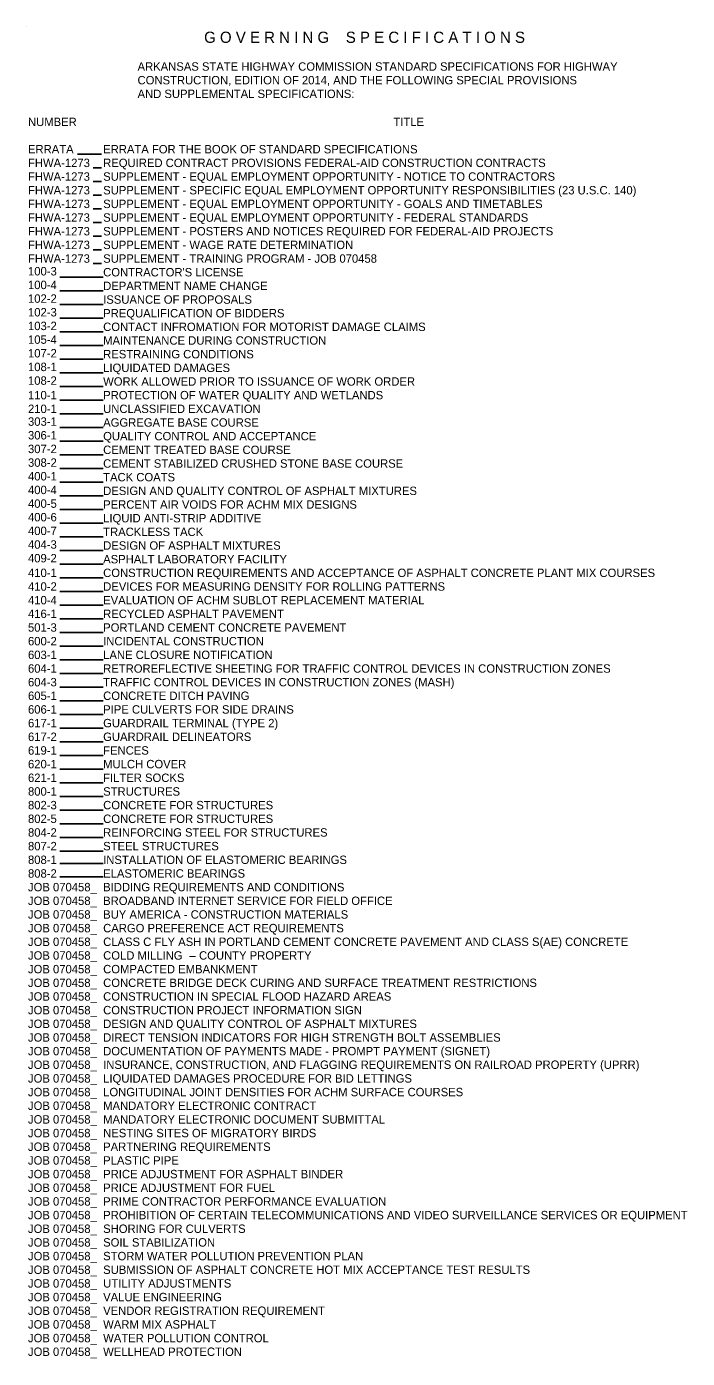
# Model space of a CAD drawing. Extents: x -2857 to 1648, y -1031 to 968.
# Drawn here: x -1360 to -417, y -932 to 968 of the extents above; entities that cross this region are included whole.
import ezdxf

# ---------------------------------------------------------------- set-up
doc = ezdxf.new("R2010")
doc.units = 0
doc.layers.add('Default', color=7, linetype='Continuous')

msp = doc.modelspace()

# ---------------------------------------------------------------- linework, layer by layer
at = {"layer": 'Default'}
for p, q in [((-1359.5, 967.9), (-1359.5, 967.9)), ((-1287.2, 785.9), (-1252.7, 785.9)), ((-1264.8, 766.4), (-1252.7, 766.4)), ((-1264.8, 746.9), (-1252.7, 746.9)), ((-1264.8, 727.4), (-1252.7, 727.4)), ((-1264.8, 707.9), (-1252.7, 707.9)), ((-1264.8, 688.4), (-1252.7, 688.4)), ((-1264.8, 668.9), (-1252.7, 668.9)), ((-1264.8, 649.4), (-1252.7, 649.4)), ((-1264.8, 629.9), (-1252.7, 629.9)), ((-1312.4, 610.4), (-1250.6, 610.4)), ((-1312.4, 590.9), (-1250.6, 590.9)), ((-1312.4, 571.4), (-1250.6, 571.4)), ((-1312.4, 551.9), (-1250.6, 551.9)), ((-1312.4, 532.4), (-1250.6, 532.4)), ((-1312.4, 512.9), (-1250.6, 512.9)), ((-1312.4, 493.4), (-1250.6, 493.4)), ((-1312.4, 473.9), (-1250.6, 473.9)), ((-1312.4, 454.4), (-1250.6, 454.4)), ((-1312.4, 434.9), (-1250.6, 434.9)), ((-1312.4, 415.4), (-1250.6, 415.4)), ((-1312.4, 395.9), (-1250.6, 395.9)), ((-1312.4, 376.4), (-1250.6, 376.4)), ((-1312.4, 356.9), (-1250.6, 356.9)), ((-1312.4, 337.4), (-1250.6, 337.4)), ((-1312.4, 317.9), (-1250.6, 317.9)), ((-1312.4, 298.4), (-1250.6, 298.4)), ((-1312.4, 278.9), (-1250.6, 278.9)), ((-1312.4, 259.4), (-1250.6, 259.4)), ((-1312.4, 239.9), (-1250.6, 239.9)), ((-1312.4, 220.4), (-1250.6, 220.4)), ((-1312.4, 200.9), (-1250.6, 200.9)), ((-1312.4, 181.4), (-1250.6, 181.4)), ((-1312.4, 161.9), (-1250.6, 161.9)), ((-1312.4, 142.4), (-1250.6, 142.4)), ((-1312.4, 122.9), (-1250.6, 122.9)), ((-1312.4, 103.4), (-1250.6, 103.4)), ((-1312.4, 83.9), (-1250.6, 83.9)), ((-1312.4, 64.4), (-1250.6, 64.4)), ((-1312.4, 44.9), (-1250.6, 44.9)), ((-1312.4, 25.4), (-1250.6, 25.4)), ((-1312.4, 5.9), (-1250.6, 5.9)), ((-1312.4, -13.6), (-1250.6, -13.6)), ((-1312.4, -33.1), (-1250.6, -33.1)), ((-1312.4, -52.6), (-1250.6, -52.6)), ((-1312.4, -72.1), (-1250.6, -72.1)), ((-1312.4, -91.6), (-1250.6, -91.6)), ((-1312.4, -111.1), (-1250.6, -111.1)), ((-1312.4, -130.6), (-1250.6, -130.6)), ((-1312.4, -150.1), (-1250.6, -150.1)), ((-1312.4, -169.6), (-1250.6, -169.6)), ((-1312.4, -189.1), (-1250.6, -189.1)), ((-1312.4, -208.6), (-1250.6, -208.6)), ((-1312.4, -226.2), (-1250.6, -226.2)), ((-1312.4, -245.3), (-1250.6, -245.3))]:
    msp.add_line(p, q, dxfattribs=at)

# ---------------------------------------------------------------- texts
for s, height, p in [('G O V E R N I N G    S P E C I F I C A T I O N S', 15.997, (-1106.4, 944.7)), ('           ARKANSAS STATE HIGHWAY COMMISSION STANDARD SPECIFICATIONS FOR HIGHWAY', 11.998, (-1250.4, 905)), ('           CONSTRUCTION, EDITION OF 2014, AND THE FOLLOWING SPECIAL PROVISIONS', 11.998, (-1250.4, 885.5)), ('           AND SUPPLEMENTAL SPECIFICATIONS:', 11.998, (-1250.4, 866)), ('NUMBER', 12, (-1357.6, 826)), ('TITLE', 12, (-836.5, 826)), ('ERRATA', 12, (-1357.6, 787)), ('ERRATA FOR THE BOOK OF STANDARD SPECIFICATIONS', 11.998, (-1250.4, 787)), ('FHWA-1273', 12, (-1357.6, 767.5)), ('REQUIRED CONTRACT PROVISIONS FEDERAL-AID CONSTRUCTION CONTRACTS', 11.998, (-1250.4, 767.5)), ('FHWA-1273', 12, (-1357.6, 748)), ('SUPPLEMENT - EQUAL EMPLOYMENT OPPORTUNITY - NOTICE TO CONTRACTORS', 11.998, (-1250.4, 748)), ('SUPPLEMENT - SPECIFIC EQUAL EMPLOYMENT OPPORTUNITY RESPONSIBILITIES (23 U.S.C. 140)', 11.998, (-1250.4, 728.5)), ('FHWA-1273', 12, (-1357.6, 728.5)), ('FHWA-1273', 12, (-1357.6, 709)), ('SUPPLEMENT - EQUAL EMPLOYMENT OPPORTUNITY - GOALS AND TIMETABLES ', 11.998, (-1250.4, 709)), ('FHWA-1273', 12, (-1357.6, 689.5)), ('SUPPLEMENT - EQUAL EMPLOYMENT OPPORTUNITY - FEDERAL STANDARDS', 11.998, (-1250.4, 689.5)), ('FHWA-1273', 12, (-1357.6, 670)), ('SUPPLEMENT - POSTERS AND NOTICES REQUIRED FOR FEDERAL-AID PROJECTS', 11.998, (-1250.4, 670)), ('FHWA-1273', 12, (-1357.6, 650.5)), ('SUPPLEMENT - WAGE RATE DETERMINATION', 11.998, (-1250.4, 650.5)), ('FHWA-1273', 12, (-1357.6, 631)), ('SUPPLEMENT - TRAINING PROGRAM - JOB 070458', 11.998, (-1250.4, 631)), ('100-3', 12, (-1357.6, 612.9)), ("CONTRACTOR'S LICENSE", 11.998, (-1250.4, 611.5)), ('100-4', 12, (-1357.6, 593.4)), ('DEPARTMENT NAME CHANGE', 11.998, (-1250.4, 592)), ('102-2', 12, (-1357.6, 573.9)), ('ISSUANCE OF PROPOSALS', 11.998, (-1250.4, 572.5)), ('102-3', 12, (-1357.6, 554.4)), ('PREQUALIFICATION OF BIDDERS', 11.998, (-1250.4, 553)), ('103-2', 12, (-1357.6, 534.9)), ('CONTACT INFROMATION FOR MOTORIST DAMAGE CLAIMS', 11.998, (-1250.4, 533.6)), ('105-4', 12, (-1357.6, 515.4)), ('MAINTENANCE DURING CONSTRUCTION', 11.998, (-1250.4, 514.1)), ('107-2', 12, (-1357.6, 495.9)), ('RESTRAINING CONDITIONS', 11.998, (-1250.4, 494.6)), ('108-1', 12, (-1357.6, 476.4)), ('LIQUIDATED DAMAGES', 11.998, (-1250.4, 475.1)), ('108-2', 12, (-1357.6, 456.9)), ('WORK ALLOWED PRIOR TO ISSUANCE OF WORK ORDER', 11.998, (-1250.4, 455.6)), ('110-1', 12, (-1357.6, 436.1)), ('PROTECTION OF WATER QUALITY AND WETLANDS', 11.998, (-1250.4, 436.1)), ('210-1', 12, (-1357.6, 416.6)), ('UNCLASSIFIED EXCAVATION', 11.998, (-1250.4, 416.6)), ('303-1', 12, (-1357.6, 398.4)), ('AGGREGATE BASE COURSE', 11.998, (-1250.4, 397.1)), ('306-1', 12, (-1357.6, 378.9)), ('QUALITY CONTROL AND ACCEPTANCE', 11.998, (-1250.4, 377.6)), ('307-2', 12, (-1357.6, 359.4)), ('CEMENT TREATED BASE COURSE', 11.998, (-1250.4, 358.1)), ('308-2', 12, (-1357.6, 339.9)), ('CEMENT STABILIZED CRUSHED STONE BASE COURSE', 11.998, (-1250.4, 338.6)), ('400-1', 12, (-1357.6, 320.4)), ('TACK COATS', 12, (-1250.4, 319.1)), ('400-4', 12, (-1357.6, 300.9)), ('DESIGN AND QUALITY CONTROL OF ASPHALT MIXTURES', 11.998, (-1250.4, 299.6)), ('400-5', 12, (-1357.6, 281.4)), ('PERCENT AIR VOIDS FOR ACHM MIX DESIGNS', 11.998, (-1250.4, 280.1)), ('400-6', 12, (-1357.6, 262)), ('LIQUID ANTI-STRIP ADDITIVE', 11.998, (-1250.4, 260.6)), ('400-7', 12, (-1357.6, 242.5)), ('TRACKLESS TACK', 11.998, (-1250.4, 241.1)), ('404-3', 12, (-1357.6, 223)), ('DESIGN OF ASPHALT MIXTURES', 11.998, (-1250.4, 221.6)), ('409-2', 12, (-1357.6, 203.5)), ('ASPHALT LABORATORY FACILITY', 11.998, (-1250.4, 202.1)), ('410-1', 12, (-1357.6, 182.6)), ('CONSTRUCTION REQUIREMENTS AND ACCEPTANCE OF ASPHALT CONCRETE PLANT MIX COURSES', 11.998, (-1250.4, 182.6)), ('410-2', 12, (-1357.6, 163.1)), ('DEVICES FOR MEASURING DENSITY FOR ROLLING PATTERNS', 11.998, (-1250.4, 163.1)), ('410-4', 12, (-1357.6, 143.6)), ('EVALUATION OF ACHM SUBLOT REPLACEMENT MATERIAL', 11.998, (-1250.4, 143.6)), ('416-1', 12, (-1357.6, 124.1)), ('RECYCLED ASPHALT PAVEMENT', 11.998, (-1250.4, 124.1)), ('501-3', 12, (-1357.6, 104.6)), ('PORTLAND CEMENT CONCRETE PAVEMENT', 11.998, (-1250.4, 104.6)), ('600-2', 12, (-1357.6, 85.1)), ('INCIDENTAL CONSTRUCTION', 11.998, (-1250.4, 85.1)), ('603-1', 12, (-1357.6, 65.6)), ('LANE CLOSURE NOTIFICATION', 11.998, (-1250.4, 65.6)), ('604-1', 12, (-1357.6, 46.1)), ('RETROREFLECTIVE SHEETING FOR TRAFFIC CONTROL DEVICES IN CONSTRUCTION ZONES', 11.998, (-1250.4, 46.1)), ('604-3', 12, (-1357.6, 26.6)), ('TRAFFIC CONTROL DEVICES IN CONSTRUCTION ZONES (MASH)', 11.998, (-1250.4, 26.6)), ('605-1', 12, (-1357.6, 7.2)), ('CONCRETE DITCH PAVING', 11.998, (-1250.4, 7.2)), ('606-1', 12, (-1357.6, -12.3)), ('PIPE CULVERTS FOR SIDE DRAINS', 11.998, (-1250.4, -12.3)), ('617-1', 12, (-1357.6, -31.8)), ('GUARDRAIL TERMINAL (TYPE 2)', 11.998, (-1250.4, -31.8)), ('617-2', 12, (-1357.6, -51.3)), ('GUARDRAIL DELINEATORS', 11.998, (-1250.4, -51.3)), ('619-1', 12, (-1357.6, -70.8)), ('FENCES', 12, (-1250.4, -70.8)), ('620-1', 12, (-1357.6, -90.3)), ('MULCH COVER', 11.998, (-1250.4, -90.3)), ('621-1', 12, (-1357.6, -109.8)), ('FILTER SOCKS', 11.998, (-1250.4, -109.8)), ('800-1', 12, (-1357.6, -129.3)), ('STRUCTURES', 12, (-1250.4, -129.3)), ('802-3', 12, (-1357.6, -148.8)), ('CONCRETE FOR STRUCTURES', 11.998, (-1250.4, -148.8)), ('802-5', 12, (-1357.6, -168.3)), ('CONCRETE FOR STRUCTURES', 11.998, (-1250.4, -168.3)), ('804-2', 12, (-1357.6, -187.8)), ('REINFORCING STEEL FOR STRUCTURES', 11.998, (-1250.4, -187.8)), ('807-2', 12, (-1357.6, -207.3)), ('STEEL STRUCTURES', 11.998, (-1250.4, -207.3)), ('808-1', 12, (-1357.6, -226.8)), ('INSTALLATION OF ELASTOMERIC BEARINGS', 11.998, (-1250.4, -226.8)), ('808-2', 12, (-1357.6, -246.3)), ('ELASTOMERIC BEARINGS', 11.998, (-1250.4, -246.3)), ('JOB 070458_', 11.998, (-1357.6, -265.8)), ('BIDDING REQUIREMENTS AND CONDITIONS', 11.998, (-1250.4, -265.8)), ('JOB 070458_', 11.998, (-1357.6, -285.3)), ('BROADBAND INTERNET SERVICE FOR FIELD OFFICE', 11.998, (-1250.4, -285.3)), ('JOB 070458_', 11.998, (-1357.6, -304.8)), ('BUY AMERICA - CONSTRUCTION MATERIALS', 11.998, (-1250.4, -304.8)), ('JOB 070458_', 11.998, (-1357.6, -324.3)), ('CARGO PREFERENCE ACT REQUIREMENTS', 11.998, (-1250.4, -324.3)), ('JOB 070458_', 11.998, (-1357.6, -343.8)), ('CLASS C FLY ASH IN PORTLAND CEMENT CONCRETE PAVEMENT AND CLASS S(AE) CONCRETE', 11.998, (-1250.4, -343.8)), ('JOB 070458_', 11.998, (-1357.6, -363.3)), ('COLD MILLING ', 11.998, (-1250.4, -363.3)), ('–', 12, (-1127.4, -363.3)), (' COUNTY PROPERTY', 11.998, (-1118.1, -363.3)), ('JOB 070458_', 11.998, (-1357.6, -382.8)), ('COMPACTED EMBANKMENT', 11.998, (-1250.4, -382.8)), ('JOB 070458_', 11.998, (-1357.6, -402.3)), ('CONCRETE BRIDGE DECK CURING AND SURFACE TREATMENT RESTRICTIONS', 11.998, (-1250.4, -402.3)), ('JOB 070458_', 11.998, (-1357.6, -421.8)), ('CONSTRUCTION IN SPECIAL FLOOD HAZARD AREAS', 11.998, (-1250.4, -421.8)), ('JOB 070458_', 11.998, (-1357.6, -441.3)), ('CONSTRUCTION PROJECT INFORMATION SIGN', 11.998, (-1250.4, -441.3)), ('JOB 070458_', 11.998, (-1357.6, -460.8)), ('DESIGN AND QUALITY CONTROL OF ASPHALT MIXTURES', 11.998, (-1250.4, -460.8)), ('JOB 070458_', 11.998, (-1357.6, -480.3)), ('DIRECT TENSION INDICATORS FOR HIGH STRENGTH BOLT ASSEMBLIES', 11.998, (-1250.4, -480.3)), ('JOB 070458_', 11.998, (-1357.6, -499.8)), ('DOCUMENTATION OF PAYMENTS MADE - PROMPT PAYMENT (SIGNET)', 11.998, (-1250.4, -499.8)), ('JOB 070458_', 11.998, (-1357.6, -519.2)), ('INSURANCE, CONSTRUCTION, AND FLAGGING REQUIREMENTS ON RAILROAD PROPERTY (UPRR)', 11.998, (-1250.4, -519.2)), ('JOB 070458_', 11.998, (-1357.6, -538.7)), ('LIQUIDATED DAMAGES PROCEDURE FOR BID LETTINGS', 11.998, (-1250.4, -538.7)), ('JOB 070458_', 11.998, (-1357.6, -558.2)), ('LONGITUDINAL JOINT DENSITIES FOR ACHM SURFACE COURSES', 11.998, (-1250.4, -558.2)), ('JOB 070458_', 11.998, (-1357.6, -577.7)), ('MANDATORY ELECTRONIC CONTRACT', 11.998, (-1250.4, -577.7)), ('JOB 070458_', 11.998, (-1357.6, -597.2)), ('MANDATORY ELECTRONIC DOCUMENT SUBMITTAL', 11.998, (-1250.4, -597.2)), ('JOB 070458_', 11.998, (-1357.6, -616.7)), ('NESTING SITES OF MIGRATORY BIRDS', 11.998, (-1250.4, -616.7)), ('JOB 070458_', 11.998, (-1357.6, -636.2)), ('PARTNERING REQUIREMENTS ', 11.998, (-1250.4, -636.2)), ('JOB 070458_', 11.998, (-1357.6, -655.7)), ('PLASTIC PIPE', 11.998, (-1250.4, -655.7)), ('JOB 070458_', 11.998, (-1357.6, -675.2)), ('PRICE ADJUSTMENT FOR ASPHALT BINDER', 11.998, (-1250.4, -675.2)), ('JOB 070458_', 11.998, (-1357.6, -694.7)), ('PRICE ADJUSTMENT FOR FUEL', 11.998, (-1250.4, -694.7)), ('JOB 070458_', 11.998, (-1357.6, -714.2)), ('PRIME CONTRACTOR PERFORMANCE EVALUATION', 11.998, (-1250.4, -714.2)), ('JOB 070458_', 11.998, (-1357.6, -733.7)), ('PROHIBITION OF CERTAIN TELECOMMUNICATIONS AND VIDEO SURVEILLANCE SERVICES OR EQUIPMENT', 11.998, (-1250.4, -733.7)), ('JOB 070458_', 11.998, (-1357.6, -753.2)), ('SHORING FOR CULVERTS', 11.998, (-1250.4, -753.2)), ('JOB 070458_', 11.998, (-1357.6, -772.7)), ('SOIL STABILIZATION', 11.998, (-1250.4, -772.7)), ('JOB 070458_', 11.998, (-1357.6, -792.2)), ('STORM WATER POLLUTION PREVENTION PLAN', 11.998, (-1250.4, -792.2)), ('JOB 070458_', 11.998, (-1357.6, -811.7)), ('SUBMISSION OF ASPHALT CONCRETE HOT MIX ACCEPTANCE TEST RESULTS', 11.998, (-1250.4, -811.7)), ('JOB 070458_', 11.998, (-1357.6, -831.2)), ('UTILITY ADJUSTMENTS', 11.998, (-1250.4, -831.2)), ('JOB 070458_', 11.998, (-1357.6, -850.7)), ('VALUE ENGINEERING', 11.998, (-1250.4, -850.7)), ('JOB 070458_', 11.998, (-1357.6, -870.2)), ('VENDOR REGISTRATION REQUIREMENT', 11.998, (-1250.4, -870.2)), ('JOB 070458_', 11.998, (-1357.6, -889.7)), ('WARM MIX ASPHALT', 11.998, (-1250.4, -889.7)), ('JOB 070458_', 11.998, (-1357.6, -909.2)), ('WATER POLLUTION CONTROL', 11.998, (-1250.4, -909.2)), ('JOB 070458_', 11.998, (-1357.6, -928.7)), ('WELLHEAD PROTECTION', 11.998, (-1250.4, -928.7))]:
    msp.add_text(s, height=height, dxfattribs=at).set_placement(p)

doc.saveas('drawing.dxf')
